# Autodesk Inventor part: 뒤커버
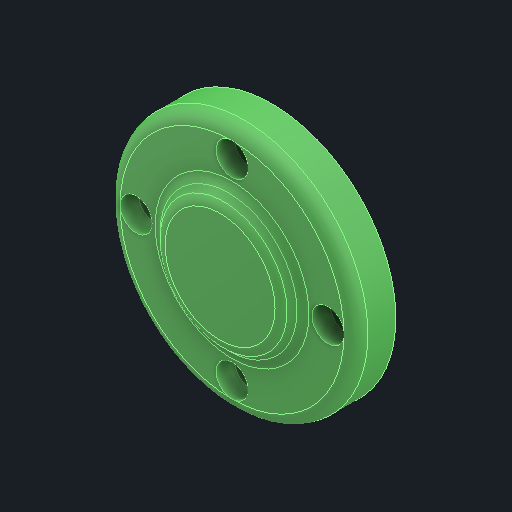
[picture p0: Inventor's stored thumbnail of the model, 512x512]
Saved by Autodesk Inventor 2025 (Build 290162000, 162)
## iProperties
Created: 2025-08
Part Number: 뒤커버
Material: 알루미늄 6061
Document SubType Name: Modeling
Designer: infra15
Density: 2.71 g/cm^3
Appearance: 기본값
Author: jhkim
Sending System: Autodesk Inventor 2026
Preprocessor: ST-DEVELOPER v20.1
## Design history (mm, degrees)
feature "솔리드1"
node "솔리드2"
